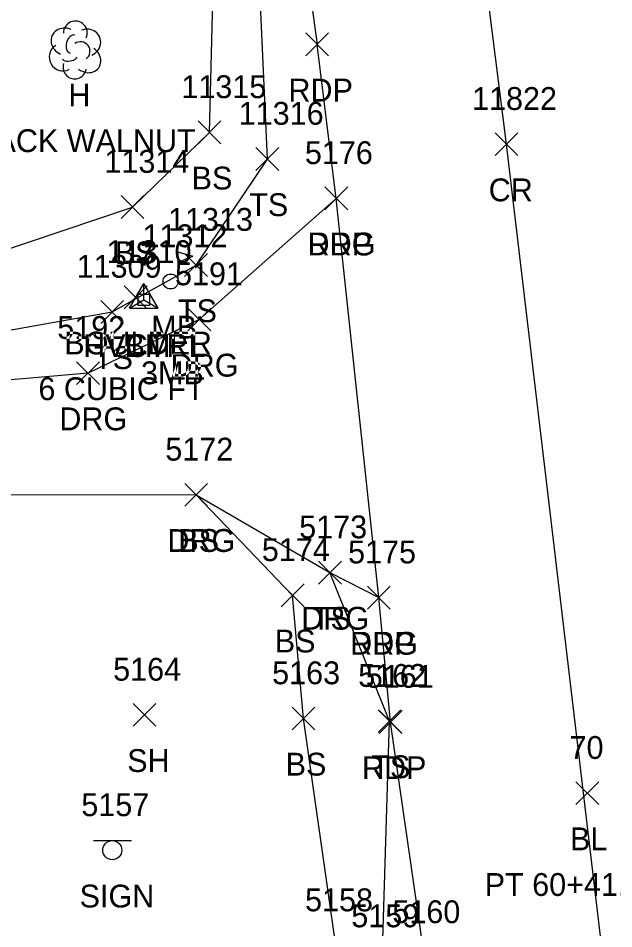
# Model space of a CAD drawing. Extents: x 1439173 to 1457902, y 641926 to 659889.
# Drawn here: x 1447904.7 to 1447956.8, y 648473.7 to 648553.4 of the extents above; entities that cross this region are included whole.
import ezdxf

# ---------------------------------------------------------------- set-up
doc = ezdxf.new("R2010")
doc.units = 0
for name, color, linetype in [('C_A', 7, 'Continuous'), ('C_C', 7, 'Continuous'), ('C_I', 7, 'Continuous'), ('C_TIC', 7, 'Continuous'), ('CPBM', 7, 'Continuous'), ('CPSM', 7, 'Continuous'), ('L_A', 7, 'Continuous'), ('L_C', 7, 'Continuous'), ('L_I', 7, 'Continuous'), ('L_TIC', 7, 'Continuous'), ('LELB', 7, 'Continuous'), ('LMB', 7, 'Continuous'), ('LTD', 7, 'Continuous'), ('P_A', 7, 'Continuous'), ('P_I', 7, 'Continuous'), ('P_TIC', 7, 'Continuous'), ('PET', 7, 'Continuous'), ('PRC', 7, 'Continuous'), ('R_A', 7, 'Continuous'), ('R_I', 7, 'Continuous'), ('R_TIC', 7, 'Continuous'), ('RDG', 7, 'Continuous'), ('S_A', 7, 'Continuous'), ('S_I', 7, 'Continuous'), ('SSGN', 7, 'Continuous')]:
    doc.layers.add(name, color=color, linetype=linetype)

msp = doc.modelspace()

# ---------------------------------------------------------------- linework, layer by layer
at = {"layer": 'C_TIC'}
for points in [[(1447953.508, 648484.546), (1447955.508, 648486.546)], [(1447955.508, 648484.546), (1447953.508, 648486.546)]]:
    msp.add_lwpolyline(points, dxfattribs=at)
at = {"layer": 'CPBM'}
for p, q in [((1447915.164, 648528.245), (1447915.164, 648529.245)), ((1447915.164, 648529.245), (1447916.164, 648529.245)), ((1447915.164, 648528.245), (1447915.164, 648529.245)), ((1447915.164, 648529.245), (1447916.164, 648529.245)), ((1447915.164, 648528.245), (1447915.164, 648529.245)), ((1447915.164, 648529.245), (1447916.164, 648529.245)), ((1447915.164, 648528.245), (1447915.164, 648529.245)), ((1447915.164, 648529.245), (1447916.164, 648529.245)), ((1447915.164, 648528.245), (1447915.164, 648529.245)), ((1447915.164, 648529.245), (1447916.164, 648529.245)), ((1447915.164, 648528.245), (1447915.164, 648529.245)), ((1447915.164, 648529.245), (1447916.164, 648529.245)), ((1447916.164, 648529.245), (1447916.164, 648528.245)), ((1447916.164, 648529.245), (1447916.164, 648528.245)), ((1447916.164, 648529.245), (1447916.164, 648528.245)), ((1447916.164, 648529.245), (1447916.164, 648528.245)), ((1447916.164, 648529.245), (1447916.164, 648528.245)), ((1447916.164, 648529.245), (1447916.164, 648528.245)), ((1447915.667, 648528.746), (1447915.667, 648528.746)), ((1447915.667, 648528.746), (1447915.667, 648528.746)), ((1447915.667, 648528.746), (1447915.667, 648528.746)), ((1447915.667, 648528.746), (1447915.667, 648528.746)), ((1447915.667, 648528.746), (1447915.667, 648528.746)), ((1447915.667, 648528.746), (1447915.667, 648528.746)), ((1447915.667, 648528.746), (1447915.667, 648528.746)), ((1447915.667, 648528.746), (1447915.667, 648528.746)), ((1447915.667, 648528.746), (1447915.667, 648528.746)), ((1447915.667, 648528.746), (1447915.667, 648528.746)), ((1447915.667, 648528.746), (1447915.667, 648528.746)), ((1447915.667, 648528.746), (1447915.667, 648528.746)), ((1447916.164, 648528.245), (1447915.164, 648528.245)), ((1447916.164, 648528.245), (1447915.164, 648528.245)), ((1447916.164, 648528.245), (1447915.164, 648528.245)), ((1447916.164, 648528.245), (1447915.164, 648528.245)), ((1447916.164, 648528.245), (1447915.164, 648528.245)), ((1447916.164, 648528.245), (1447915.164, 648528.245))]:
    msp.add_line(p, q, dxfattribs=at)
at = {"layer": 'CPSM'}
for p, q in [((1447914.417, 648528.025), (1447915.667, 648530.19)), ((1447914.417, 648528.025), (1447915.667, 648530.19)), ((1447914.417, 648528.025), (1447915.667, 648530.19)), ((1447914.417, 648528.025), (1447915.667, 648530.19)), ((1447914.417, 648528.025), (1447915.667, 648530.19)), ((1447914.417, 648528.025), (1447915.667, 648530.19)), ((1447916.917, 648528.025), (1447915.667, 648530.19)), ((1447915.667, 648528.746), (1447915.667, 648530.19)), ((1447916.917, 648528.025), (1447915.667, 648530.19)), ((1447915.667, 648528.746), (1447915.667, 648530.19)), ((1447916.917, 648528.025), (1447915.667, 648530.19)), ((1447915.667, 648528.746), (1447915.667, 648530.19)), ((1447916.917, 648528.025), (1447915.667, 648530.19)), ((1447915.667, 648528.746), (1447915.667, 648530.19)), ((1447916.917, 648528.025), (1447915.667, 648530.19)), ((1447915.667, 648528.746), (1447915.667, 648530.19)), ((1447916.917, 648528.025), (1447915.667, 648530.19)), ((1447915.667, 648528.746), (1447915.667, 648530.19)), ((1447914.417, 648528.025), (1447915.667, 648528.746)), ((1447914.417, 648528.025), (1447915.667, 648528.746)), ((1447914.417, 648528.025), (1447915.667, 648528.746)), ((1447914.417, 648528.025), (1447915.667, 648528.746)), ((1447914.417, 648528.025), (1447915.667, 648528.746)), ((1447914.417, 648528.025), (1447915.667, 648528.746)), ((1447915.667, 648528.746), (1447915.667, 648528.746)), ((1447915.667, 648528.746), (1447916.917, 648528.025)), ((1447915.667, 648528.746), (1447915.667, 648528.746)), ((1447915.667, 648528.746), (1447916.917, 648528.025)), ((1447915.667, 648528.746), (1447915.667, 648528.746)), ((1447915.667, 648528.746), (1447916.917, 648528.025)), ((1447915.667, 648528.746), (1447915.667, 648528.746)), ((1447915.667, 648528.746), (1447916.917, 648528.025)), ((1447915.667, 648528.746), (1447915.667, 648528.746)), ((1447915.667, 648528.746), (1447916.917, 648528.025)), ((1447915.667, 648528.746), (1447915.667, 648528.746)), ((1447915.667, 648528.746), (1447916.917, 648528.025)), ((1447914.417, 648528.025), (1447916.917, 648528.025)), ((1447914.417, 648528.025), (1447916.917, 648528.025)), ((1447914.417, 648528.025), (1447916.917, 648528.025)), ((1447914.417, 648528.025), (1447916.917, 648528.025)), ((1447914.417, 648528.025), (1447916.917, 648528.025)), ((1447914.417, 648528.025), (1447916.917, 648528.025))]:
    msp.add_line(p, q, dxfattribs=at)
at = {"layer": 'L_TIC'}
for points in [[(1447920.414, 648542.418), (1447922.414, 648544.418)], [(1447922.414, 648542.418), (1447920.414, 648544.418)], [(1447925.492, 648540.086), (1447927.492, 648542.086)], [(1447927.492, 648540.086), (1447925.492, 648542.086)], [(1447913.677, 648535.879), (1447915.677, 648537.879)], [(1447915.677, 648535.879), (1447913.677, 648537.879)], [(1447919.244, 648530.798), (1447921.244, 648532.798)], [(1447921.244, 648530.798), (1447919.244, 648532.798)], [(1447913.947, 648527.97), (1447915.947, 648529.97)], [(1447915.947, 648527.97), (1447913.947, 648529.97)], [(1447911.891, 648526.692), (1447913.891, 648528.692)], [(1447913.891, 648526.692), (1447911.891, 648528.692)], [(1447919.246, 648510.675), (1447921.246, 648512.675)], [(1447921.246, 648510.675), (1447919.246, 648512.675)], [(1447930.97, 648503.865), (1447932.97, 648505.865)], [(1447932.97, 648503.865), (1447930.97, 648505.865)], [(1447927.699, 648501.871), (1447929.699, 648503.871)], [(1447929.699, 648501.871), (1447927.699, 648503.871)], [(1447927.699, 648501.871), (1447929.699, 648503.871)], [(1447929.699, 648501.871), (1447927.699, 648503.871)], [(1447914.723, 648491.401), (1447916.723, 648493.401)], [(1447916.723, 648491.401), (1447914.723, 648493.401)], [(1447928.649, 648491.086), (1447930.649, 648493.086)], [(1447930.649, 648491.086), (1447928.649, 648493.086)], [(1447936.184, 648490.856), (1447938.184, 648492.856)], [(1447938.184, 648490.856), (1447936.184, 648492.856)]]:
    msp.add_lwpolyline(points, dxfattribs=at)
at = {"layer": 'LELB'}
for points in [[(1447857.922, 648532.037), (1447874.334, 648528.105), (1447893.566, 648529.776), (1447914.677, 648536.879), (1447921.414, 648543.418), (1447921.85, 648560.743), (1447920.344, 648585.986), (1447914.482, 648614.569), (1447909.222, 648666.968), (1447905.3, 648694.716), (1447898.391, 648708.602)], [(1447874.334, 648528.105), (1447895.679, 648524.624), (1447912.891, 648527.692), (1447920.244, 648531.798), (1447926.492, 648541.086), (1447925.565, 648561.747), (1447922.67, 648586.464), (1447919.133, 648615.291), (1447912.372, 648669.649), (1447909.66, 648697.052)], [(1447920.246, 648511.675), (1447928.699, 648502.871)], [(1447948.59, 648388.591), (1447945.498, 648409.598), (1447942.339, 648430.448), (1447940.67, 648446.417), (1447936.54, 648470.802), (1447937.184, 648491.856), (1447931.97, 648504.865)], [(1447945.525, 648388.373), (1447942.958, 648409.236), (1447940.475, 648428.321), (1447938.942, 648444.357), (1447932.483, 648472.201), (1447929.649, 648492.086), (1447928.699, 648502.871)]]:
    msp.add_lwpolyline(points, dxfattribs=at)
at = {"layer": 'LMB'}
for p, q in [((1447918.659, 648532.96), (1447919.953, 648532.579)), ((1447918.665, 648530.368), (1447918.664, 648532.963)), ((1447918.664, 648532.061), (1447919.947, 648532.569)), ((1447918.009, 648530.36), (1447918.009, 648530.36))]:
    msp.add_line(p, q, dxfattribs=at)
msp.add_circle((1447918.009, 648530.36), 0.656, dxfattribs=at)
at = {"layer": 'LTD'}
msp.add_line((1447909.626, 648550.692), (1447909.626, 648550.692), dxfattribs=at)
msp.add_line((1447909.626, 648550.692), (1447909.626, 648550.692), dxfattribs=at)
msp.add_arc((1447909.672, 648552.126), 1.047, 335.52715, 180.95627, dxfattribs=at)
for centre, major_axis, ratio, start_param, end_param in [((1447908.834, 648551.359), (1.21, -0.512), 0.895232, 1.570796, 4.712389), ((1447910.667, 648551.276), (-1.141, -0.483), 0.949671, 1.570796, 4.712389), ((1447909.417, 648551.151), (-0.208, -0.792), 0.645439, 3.141593, 6.283185), ((1447908.542, 648549.984), (0.584, -1.042), 0.959034, 3.141593, 6.283185), ((1447910.126, 648550.526), (-0.5, 0.667), 0.989748, 3.141593, 6.283185), ((1447910.626, 648549.859), (-1.09, 0.792), 0.841452, 1.570796, 4.712389), ((1447909.167, 648549.942), (-0.625, -0.083), 0.423636, 0, 3.141593), ((1447909.626, 648549.192), (0.265, 1.061), 0.942809, 1.570796, 4.712389)]:
    msp.add_ellipse(centre, major_axis=major_axis, ratio=ratio, start_param=start_param, end_param=end_param, dxfattribs=at)
at = {"layer": 'P_TIC'}
for points in [[(1447929.849, 648550.124), (1447931.849, 648552.124)], [(1447931.849, 648550.124), (1447929.849, 648552.124)], [(1447946.44, 648541.384), (1447948.44, 648543.384)], [(1447948.44, 648541.384), (1447946.44, 648543.384)], [(1447931.524, 648536.643), (1447933.524, 648538.643)], [(1447933.524, 648536.643), (1447931.524, 648538.643)], [(1447935.25, 648501.671), (1447937.25, 648503.671)], [(1447937.25, 648501.671), (1447935.25, 648503.671)], [(1447936.285, 648490.774), (1447938.285, 648492.774)], [(1447938.285, 648490.774), (1447936.285, 648492.774)]]:
    msp.add_lwpolyline(points, dxfattribs=at)
at = {"layer": 'PET'}
for points in [[(1447925.254, 648591.915), (1447930.849, 648551.124)], [(1447951.667, 648388.495), (1447948.364, 648410.154), (1447945.479, 648430.81), (1447945.518, 648431.583), (1447942.919, 648446.701), (1447940.264, 648471.16), (1447937.285, 648491.774), (1447936.25, 648502.671), (1447932.524, 648537.643), (1447930.849, 648551.124)]]:
    msp.add_lwpolyline(points, dxfattribs=at)
at = {"layer": 'PRC'}
msp.add_lwpolyline([(1448032.328, 647961.695), (1448025.033, 648003.456), (1448015.667, 648063.56), (1448008.207, 648110.034), (1448001.08, 648156.365), (1447993.035, 648207.402), (1447985.395, 648256.522), (1447977.626, 648310.23), (1447970.828, 648357.733), (1447966.46, 648396.633), (1447963.745, 648410.578), (1447956.838, 648463.171), (1447947.44, 648542.384), (1447940.666, 648596.002), (1447933.626, 648644.512), (1447928.191, 648688.314), (1447922.05, 648736.929), (1447916.642, 648778.151)], dxfattribs=at)
at = {"layer": 'R_TIC'}
for points in [[(1447931.524, 648536.643), (1447933.524, 648538.643)], [(1447933.524, 648536.643), (1447931.524, 648538.643)], [(1447919.528, 648526.03), (1447921.528, 648528.03)], [(1447921.528, 648526.03), (1447919.528, 648528.03)], [(1447909.78, 648521.331), (1447911.78, 648523.331)], [(1447911.78, 648521.331), (1447909.78, 648523.331)], [(1447919.246, 648510.675), (1447921.246, 648512.675)], [(1447921.246, 648510.675), (1447919.246, 648512.675)], [(1447930.97, 648503.865), (1447932.97, 648505.865)], [(1447932.97, 648503.865), (1447930.97, 648505.865)], [(1447935.25, 648501.671), (1447937.25, 648503.671)], [(1447937.25, 648501.671), (1447935.25, 648503.671)]]:
    msp.add_lwpolyline(points, dxfattribs=at)
at = {"layer": 'RDG'}
for points in [[(1447932.524, 648537.643), (1447920.528, 648527.03), (1447910.78, 648522.331), (1447885.439, 648520.156), (1447862.686, 648518.92), (1447848.044, 648518.375), (1447821.448, 648517.145), (1447798.723, 648510.765), (1447799.039, 648497.584), (1447795.002, 648486.04), (1447781.779, 648484.446)], [(1447785.884, 648452.994), (1447803.737, 648456.186), (1447804.418, 648477.221), (1447820.826, 648498.801), (1447848.929, 648504.762), (1447875.017, 648509.98), (1447899.515, 648511.701), (1447920.246, 648511.675), (1447931.97, 648504.865), (1447936.25, 648502.671)]]:
    msp.add_lwpolyline(points, dxfattribs=at)
at = {"layer": 'SSGN'}
for p, q in [((1447911.26, 648481.387), (1447914.593, 648481.387)), ((1447912.907, 648480.554), (1447912.907, 648480.554))]:
    msp.add_line(p, q, dxfattribs=at)
msp.add_circle((1447912.907, 648480.554), 0.833, dxfattribs=at)

# ---------------------------------------------------------------- texts
at = {"layer": 'C_A'}
for s, p in [('HVCTRL', (1447910.36, 648523.746)), ('HVCTRL', (1447910.36, 648523.746)), ('HVCTRL', (1447910.36, 648523.746)), ('HVCTRL', (1447910.36, 648523.746)), ('HVCTRL', (1447910.36, 648523.746)), ('HVCTRL', (1447910.36, 648523.746)), ('BM', (1447913.982, 648523.746)), ('BM', (1447913.982, 648523.746)), ('BM', (1447913.982, 648523.746)), ('BM', (1447913.982, 648523.746)), ('BM', (1447913.982, 648523.746)), ('BM', (1447913.982, 648523.746)), ('BL', (1447952.996, 648480.546))]:
    msp.add_text(s, height=2, dxfattribs=at).set_placement(p)
at = {"layer": 'C_C'}
msp.add_text('PT 60+41.39', height=2, dxfattribs=at).set_placement((1447945.524, 648476.546))
at = {"layer": 'C_I'}
for s, p in [('7', (1447915.1, 648531.746)), ('7', (1447915.1, 648531.746)), ('7', (1447915.1, 648531.746)), ('7', (1447915.1, 648531.746)), ('7', (1447915.1, 648531.746)), ('7', (1447915.1, 648531.746)), ('7', (1447915.1, 648531.746)), ('7', (1447915.1, 648531.746)), ('7', (1447915.1, 648531.746)), ('7', (1447915.1, 648531.746)), ('7', (1447915.1, 648531.746)), ('7', (1447915.1, 648531.746)), ('70', (1447952.957, 648488.546))]:
    msp.add_text(s, height=2, dxfattribs=at).set_placement(p)
at = {"layer": 'L_A'}
for s, p in [('H', (1447909.059, 648545.692)), ('BS', (1447919.855, 648538.418)), ('TS', (1447924.901, 648536.086)), ('BS', (1447913.118, 648531.879)), ('TS', (1447918.654, 648526.798)), ('MB', (1447916.317, 648525.36)), ('BOULDER', (1447908.703, 648523.97)), ('TS', (1447911.3, 648522.692)), ('BS', (1447918.687, 648506.675)), ('TS', (1447930.38, 648499.865)), ('BS', (1447927.14, 648497.871)), ('BS', (1447927.14, 648497.871)), ('SH', (1447914.211, 648487.401)), ('BS', (1447928.09, 648487.086)), ('TS', (1447935.594, 648486.856))]:
    msp.add_text(s, height=2, dxfattribs=at).set_placement(p)
at = {"layer": 'L_C'}
for s, p in [('L.BLACK WALNUT', (1447897.177, 648541.692)), ('3MB', (1447915.419, 648521.36)), ('6 CUBIC FT', (1447906.435, 648519.97))]:
    msp.add_text(s, height=2, dxfattribs=at).set_placement(p)
at = {"layer": 'L_I'}
for s, p in [('11315', (1447918.958, 648546.418)), ('11316', (1447923.98, 648544.086)), ('11314', (1447912.22, 648539.879)), ('11313', (1447917.787, 648534.798)), ('11312', (1447915.553, 648533.36)), ('11310', (1447912.404, 648531.97)), ('11309', (1447909.78, 648530.692)), ('5172', (1447917.553, 648514.675)), ('5173', (1447929.277, 648507.865)), ('5174', (1447926.006, 648505.871)), ('5174', (1447926.006, 648505.871)), ('5164', (1447912.983, 648495.401)), ('5163', (1447926.909, 648495.086)), ('5162', (1447934.444, 648494.856)), ('5158', (1447929.79, 648475.201)), ('5159', (1447933.84, 648473.802))]:
    msp.add_text(s, height=2, dxfattribs=at).set_placement(p)
at = {"layer": 'P_A'}
for s, p in [('RDP', (1447928.337, 648546.124)), ('CR', (1447945.873, 648537.384)), ('RDP', (1447930.012, 648532.643)), ('RDP', (1447933.739, 648497.671)), ('RDP', (1447934.773, 648486.774))]:
    msp.add_text(s, height=2, dxfattribs=at).set_placement(p)
at = {"layer": 'P_I'}
for s, p in [('11822', (1447944.416, 648545.384)), ('5176', (1447929.776, 648540.643)), ('5175', (1447933.558, 648505.671)), ('5161', (1447935.111, 648494.774)), ('5160', (1447937.437, 648474.16))]:
    msp.add_text(s, height=2, dxfattribs=at).set_placement(p)
at = {"layer": 'R_A'}
for p in [(1447930.012, 648532.643), (1447918.016, 648522.03), (1447908.268, 648517.331), (1447917.734, 648506.675), (1447929.458, 648499.865), (1447933.739, 648497.671)]:
    msp.add_text('DRG', height=2, dxfattribs=at).set_placement(p)
at = {"layer": 'R_I'}
for s, p in [('5176', (1447929.776, 648540.643)), ('5191', (1447918.402, 648530.03)), ('5192', (1447908.087, 648525.331)), ('5172', (1447917.553, 648514.675)), ('5173', (1447929.277, 648507.865)), ('5175', (1447933.558, 648505.671))]:
    msp.add_text(s, height=2, dxfattribs=at).set_placement(p)
at = {"layer": 'S_A'}
msp.add_text('SIGN', height=2, dxfattribs=at).set_placement((1447910.045, 648475.534))
at = {"layer": 'S_I'}
msp.add_text('5157', height=2, dxfattribs=at).set_placement((1447910.194, 648483.534))

doc.saveas('drawing.dxf')
